Omron CX-Programmer project NuevoProyecto (CX-Programmer 9.50)

# PLC NewPLC1: CP1L-E EM

## Program P3 (cyclic task 0)
Local symbols
Etapa_0 10.00 BOOL
Etapa_1 10.01 BOOL
Etapa_10 10.10 BOOL
Etapa_11 10.11 BOOL
Etapa_12 10.12 BOOL
Etapa_13 10.13 BOOL
Etapa_2 10.02 BOOL
Etapa_3 10.03 BOOL
Etapa_4 10.04 BOOL
Etapa_5 10.05 BOOL
Etapa_6 10.06 BOOL
Etapa_7 10.07 BOOL
Etapa_8 10.08 BOOL
Etapa_9 10.09 BOOL
Mb 100.01 BOOL
Md 100.02 BOOL
Mi 100.03 BOOL
Ms 100.00 BOOL
a 0.01 BOOL
b 0.02 BOOL
c 0.03 BOOL
d 0.04 BOOL
m 0.00 BOOL

### Section Sección1_Programa_principal
; Programa principal (Etapas 0 ... 13)

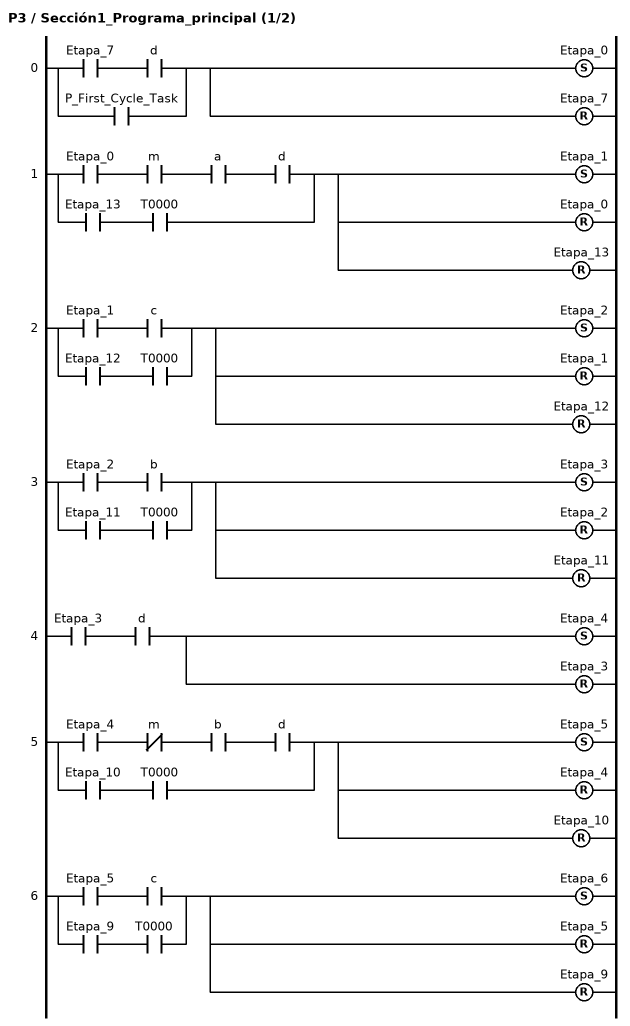
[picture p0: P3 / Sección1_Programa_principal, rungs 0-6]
; rung 0
LD Etapa_7
AND d
OR P_First_Cycle_Task
SET Etapa_0
RSET Etapa_7
; rung 1
LD Etapa_0
AND m
AND a
AND d
LD Etapa_13
AND T0000
ORLD
SET Etapa_1
RSET Etapa_0
RSET Etapa_13
; rung 2
LD Etapa_1
AND c
LD Etapa_12
AND T0000
ORLD
SET Etapa_2
RSET Etapa_1
RSET Etapa_12
; rung 3
LD Etapa_2
AND b
LD Etapa_11
AND T0000
ORLD
SET Etapa_3
RSET Etapa_2
RSET Etapa_11
; rung 4
LD Etapa_3
AND d
SET Etapa_4
RSET Etapa_3
; rung 5
LD Etapa_4
ANDNOT m
AND b
AND d
LD Etapa_10
AND T0000
ORLD
SET Etapa_5
RSET Etapa_4
RSET Etapa_10
; rung 6
LD Etapa_5
AND c
LD Etapa_9
AND T0000
ORLD
SET Etapa_6
RSET Etapa_5
RSET Etapa_9

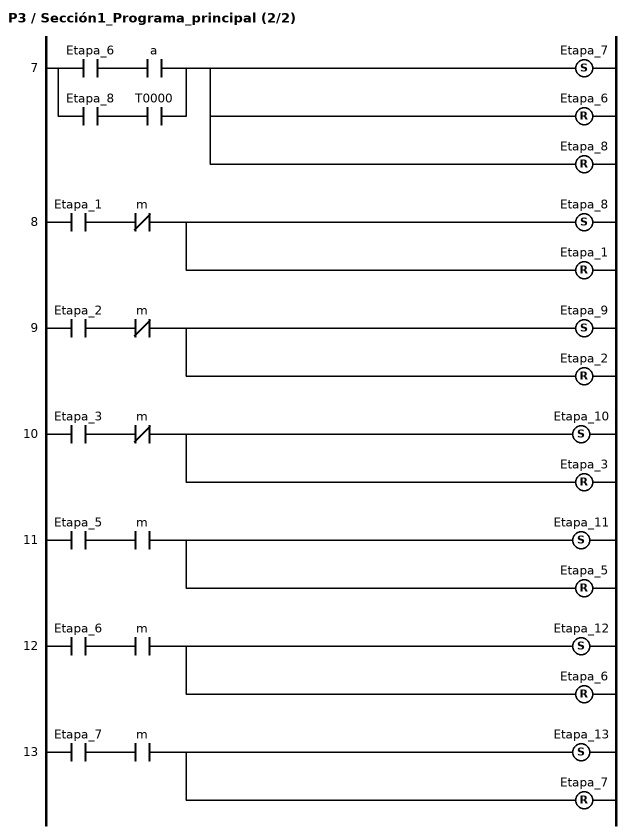
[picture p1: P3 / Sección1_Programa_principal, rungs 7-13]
; rung 7
LD Etapa_6
AND a
LD Etapa_8
AND T0000
ORLD
SET Etapa_7
RSET Etapa_6
RSET Etapa_8
; rung 8
LD Etapa_1
ANDNOT m
SET Etapa_8
RSET Etapa_1
; rung 9
LD Etapa_2
ANDNOT m
SET Etapa_9
RSET Etapa_2
; rung 10
LD Etapa_3
ANDNOT m
SET Etapa_10
RSET Etapa_3
; rung 11
LD Etapa_5
AND m
SET Etapa_11
RSET Etapa_5
; rung 12
LD Etapa_6
AND m
SET Etapa_12
RSET Etapa_6
; rung 13
LD Etapa_7
AND m
SET Etapa_13
RSET Etapa_7

### Section Sección2_Temporizador
; Las etapas van seguidas, pero no las temporizaciones con lo que se puede emplear un solo temporizador para todas las temporizaciones

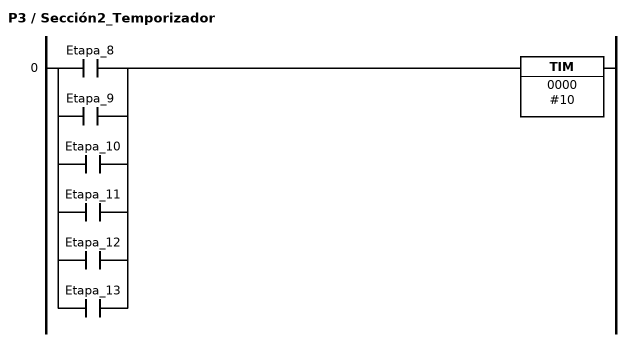
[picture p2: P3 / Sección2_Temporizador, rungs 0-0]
; rung 0
LD Etapa_8
OR Etapa_9
OR Etapa_10
OR Etapa_11
OR Etapa_12
OR Etapa_13
TIM 0000 #10

### Section Sección3_Salidas

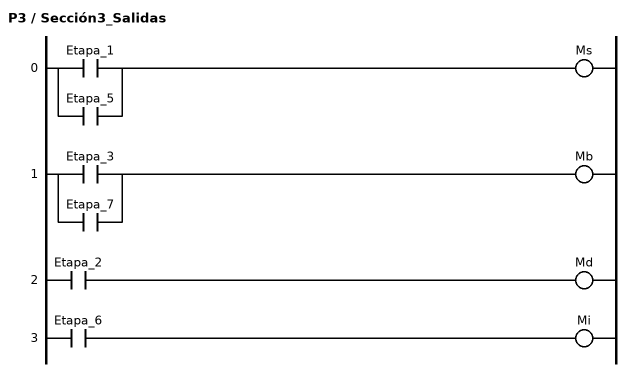
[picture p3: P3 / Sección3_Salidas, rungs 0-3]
; rung 0
LD Etapa_1
OR Etapa_5
OUT Ms
; rung 1
LD Etapa_3
OR Etapa_7
OUT Mb
; rung 2
LD Etapa_2
OUT Md
; rung 3
LD Etapa_6
OUT Mi

### Section Sección4_END
; rung 0: Fin de programa
END(001)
